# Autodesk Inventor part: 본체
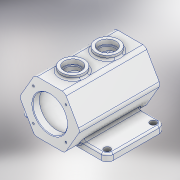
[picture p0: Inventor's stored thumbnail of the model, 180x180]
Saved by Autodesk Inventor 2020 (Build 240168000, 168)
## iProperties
Created: 2021-06
Part Number: 본체
Material: 알루미늄 6061
Document SubType Name: Modeling
Designer: 602-02
Density: 2.7 g/cm^3
Appearance: 알루미늄 - 평지
Mass: 1495.28 g
Surface Area: 1102.35 cm^2
Volume: 553.807 cm^3
Author: 602-02
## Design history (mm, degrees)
sketch "스케치1" dims "d0" = 105
  geometry: L1 (-52.5, 0)-(-26.25, 45.466); L2 (-26.25, 45.466)-(26.25, 45.466); L3 (26.25, 45.466)-(52.5, 0); L4 (52.5, 0)-(26.25, -45.466); L5 (26.25, -45.466)-(-26.25, -45.466); L6 (-26.25, -45.466)-(-52.5, 0); 4 further points
  constraints: 12 end point, 2 coincident, 1 horizontal alignment, 1 midpoint, 1 vertical alignment, 15 other
extrude "돌출1" new body sketch "스케치1" stored distance "d1" = 140; taper "d2" = 0 deg
sketch "스케치2"
  geometry: C1 r 30 at (0, 0); 1 further point
  constraints: 1 centre point, 1 coincident
  dimensions: "d3" = 60 diameter of C1
extrude "돌출2" cut sketch "스케치2" extent not by distance; stored distance "d4" = 0; taper "d5" = 0 deg
node "작업 평면1"
sketch "스케치3"
  geometry: C1 r 37.5 at (0, 0); 1 further point
  constraints: 1 centre point, 1 coincident
  dimensions: "d7" = 75 diameter of C1
extrude "돌출3" cut sketch "스케치3" distance "d8" = 116; taper "d9" = 0 deg
node "작업 평면2"
fillet "모깎기1" dims "d65" = 8
sketch "스케치4"
  geometry: L1 (26.25, 70)-(52.5, 70) reference; L2 (75, 45)-(-75, 45); L3 (-75, 45)-(-75, -55); L4 (-75, -55)-(75, -55); L5 (75, -55)-(75, 45); L6 (26.25, -70)-(-26.25, -70) reference; 2 further points
  constraints: 8 end point, 2 parallel, 1 horizontal, 1 midpoint, 1 perpendicular, 1 vertical alignment
  dimensions: "d36" = 150 distance of L3.end L4.end; "d37" = 25 distance between parallel lines of L1 L2; "d38" = 15 distance between parallel lines of L6 L4
extrude "돌출4" join sketch "스케치4" distance "d13" = 12; taper "d14" = 0 deg
node "작업 평면3"
sketch "스케치5"
  geometry: L1 (-21.631, 70)-(21.631, 70) reference; C1 r 20 at (0, 30); C2 r 20 at (0, -30); 3 further points
  constraints: 2 centre point, 2 vertical alignment
  dimensions: "d16" = 40 diameter of C1; "d17" = 40 diameter of C2; "d18" = 40 distance from line of C1.centre L1; "d19" = 60 distance of C2.centre C1.centre
extrude "돌출5" join sketch "스케치5" stored distance "d20" = 12; taper "d21" = 0 deg
sketch "스케치6"
  geometry: C1 r 20 at (0, 0) reference; C2 r 20 at (0, 60) reference; 3 further points
  constraints: 2 coincident
hole "구멍1" sketch "스케치6" at (0, 0), (0, 60) diameter "d22" = 30; stored, may be unused: countersink angle "d26" = 90 deg, drill point angle "d28" = 0 deg; dims "d23" = 6, "d24" = 4, "d25" = 2, "d27" = 8
sketch "스케치7"
  geometry: C1 r 15 at (0, 0) reference; C2 r 15 at (0, 60) reference; 3 further points
  constraints: 2 coincident
hole "구멍2" sketch "스케치7" at (0, 0), (0, 60) diameter "d29" = 25; stored, may be unused: countersink angle "d33" = 90 deg, drill point angle "d35" = 0 deg; dims "d30" = 6, "d31" = 4, "d32" = 2, "d34" = 15
sketch "스케치8"
  geometry: L1 (0, 0)-(0, 40); L2 (0, 0)-(-28.284, 28.284); A1 r 40 centre (0, 0) between (0, 40) and (-28.284, 28.284); 2 further points
  constraints: 4 end point, 2 coincident, 2 point on circle, 1 centre point, 1 vertical
  dimensions: "d39" = 80 diameter of A1; "d40" = 45 deg angle of L2 L1
hole "구멍3" sketch "스케치8" at (-28.284, 28.284) diameter "d41" = 3.242; stored, may be unused: countersink angle "d45" = 90 deg, drill point angle "d47" = 120 deg; dims "d42" = 8, "d43" = 4, "d44" = 2, "d46" = 10
sketch "스케치9"
  geometry: L1 (75, -45)-(75, 55) reference; L2 (75, 55)-(30.561, 55) reference; L3 (30.561, -45)-(75, -45) reference; L4 (-75, 55)-(-75, -45) reference; L5 (-30.561, 55)-(-75, 55) reference; L6 (-75, -45)-(-30.561, -45) reference; C1 r 5.5 at (65, 45); C2 r 5.5 at (65, -35); C3 r 5.5 at (-65, 45); C4 r 5.5 at (-65, -35); 1 further point
  constraints: 4 centre point
  dimensions: "d51" = 11 diameter of C1; "d52" = 10 distance from line of C1.centre L1; "d53" = 10 distance from line of C1.centre L2; "d56" = 11 diameter of C2; "d57" = 10 distance from line of L3 C2.centre; "d58" = 10 distance from line of C2.centre L1; "d59" = 11 diameter of C3; "d60" = 11 diameter of C4; "d61" = 10 distance from line of C3.centre L4; "d62" = 10 distance from line of C3.centre L5; "d63" = 10 distance from line of C4.centre L6; "d64" = 10 distance from line of C4.centre L4
extrude "돌출6" cut sketch "스케치9" extent not by distance; stored distance "d54" = 0; taper "d55" = 0 deg
chamfer "모따기1" distance "d66" = 1; stored, may be unused: second distance "d67" = 2, angle "d68" = 45 deg
fillet "모깎기2" dims "d69" = 5
fillet "모깎기3" dims "d73" = 3
fillet "모깎기4" dims "d74" = 10
fillet "모깎기5" dims "d75" = 3
fillet "모깎기6" dims "d76" = 3
sketch "스케치10"
  geometry: L1 (-32.293, 55)-(-65, 55) reference; L2 (-75, 45)-(-75, -35) reference; L3 (-65, -45)-(-32.293, -45) reference; 2 further points
  constraints: 1 other
  dimensions: "d92" = 50 distance from line of point (-61, 5) L3; "d93" = 14 distance from line of point (-61, 5) L2
feature "엠보싱1" sketch "스케치10" dims "d79" = 0.5, "d80" = 0
sketch "스케치11" dims "d81" = 80
  geometry: 3 further points
  constraints: 2 vertical alignment, 1 coincident, 2 other
hole "구멍4" sketch "스케치11" at (0, 40) diameter "d82" = 3.242; stored, may be unused: countersink angle "d86" = 90 deg, drill point angle "d88" = 120 deg; dims "d83" = 8, "d84" = 4, "d85" = 2, "d87" = 10
chamfer "모따기3" distance "d94" = 1; stored, may be unused: second distance "d95" = 2, angle "d96" = 45 deg
node "솔리드1"
pattern_circular "원형 패턴1" dims angle "d49" = 360 deg
pattern_circular "원형 패턴2" dims angle "d90" = 360 deg
feature "A9D066F2-1C7D-4E18-AEED-F7BC21143FA4" dims "d29" = 25, "d30" = 6, "d31" = 4, "d32" = 2, "d33" = 90 deg, "d34" = 15, "d35" = 0
other parameters: "d6" = 58, "d15" = 52.5
